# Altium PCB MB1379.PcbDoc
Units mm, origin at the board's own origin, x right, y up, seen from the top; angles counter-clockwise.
Board outline 29.13 x 44.63 mm, 2 copper layers (Top Layer, Bottom Layer), stack 1.571 mm thick; 39 components, 34 nets, 147 pads, 91 vias.
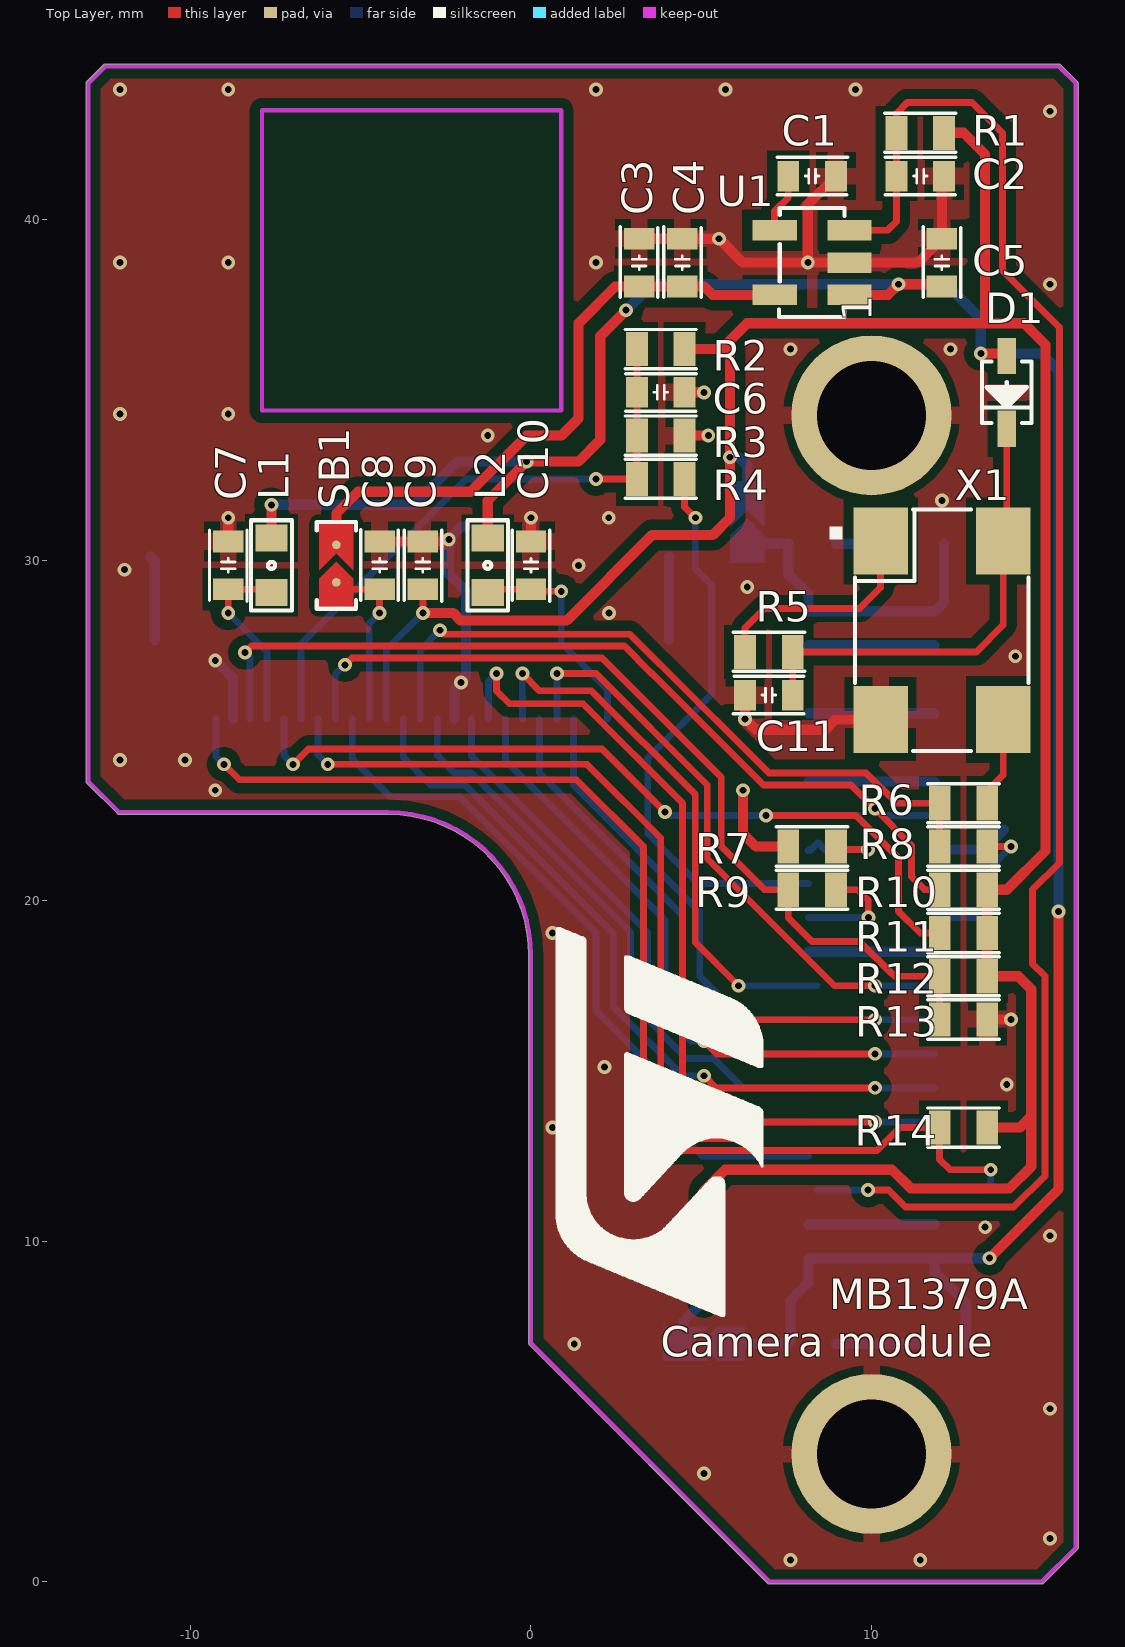
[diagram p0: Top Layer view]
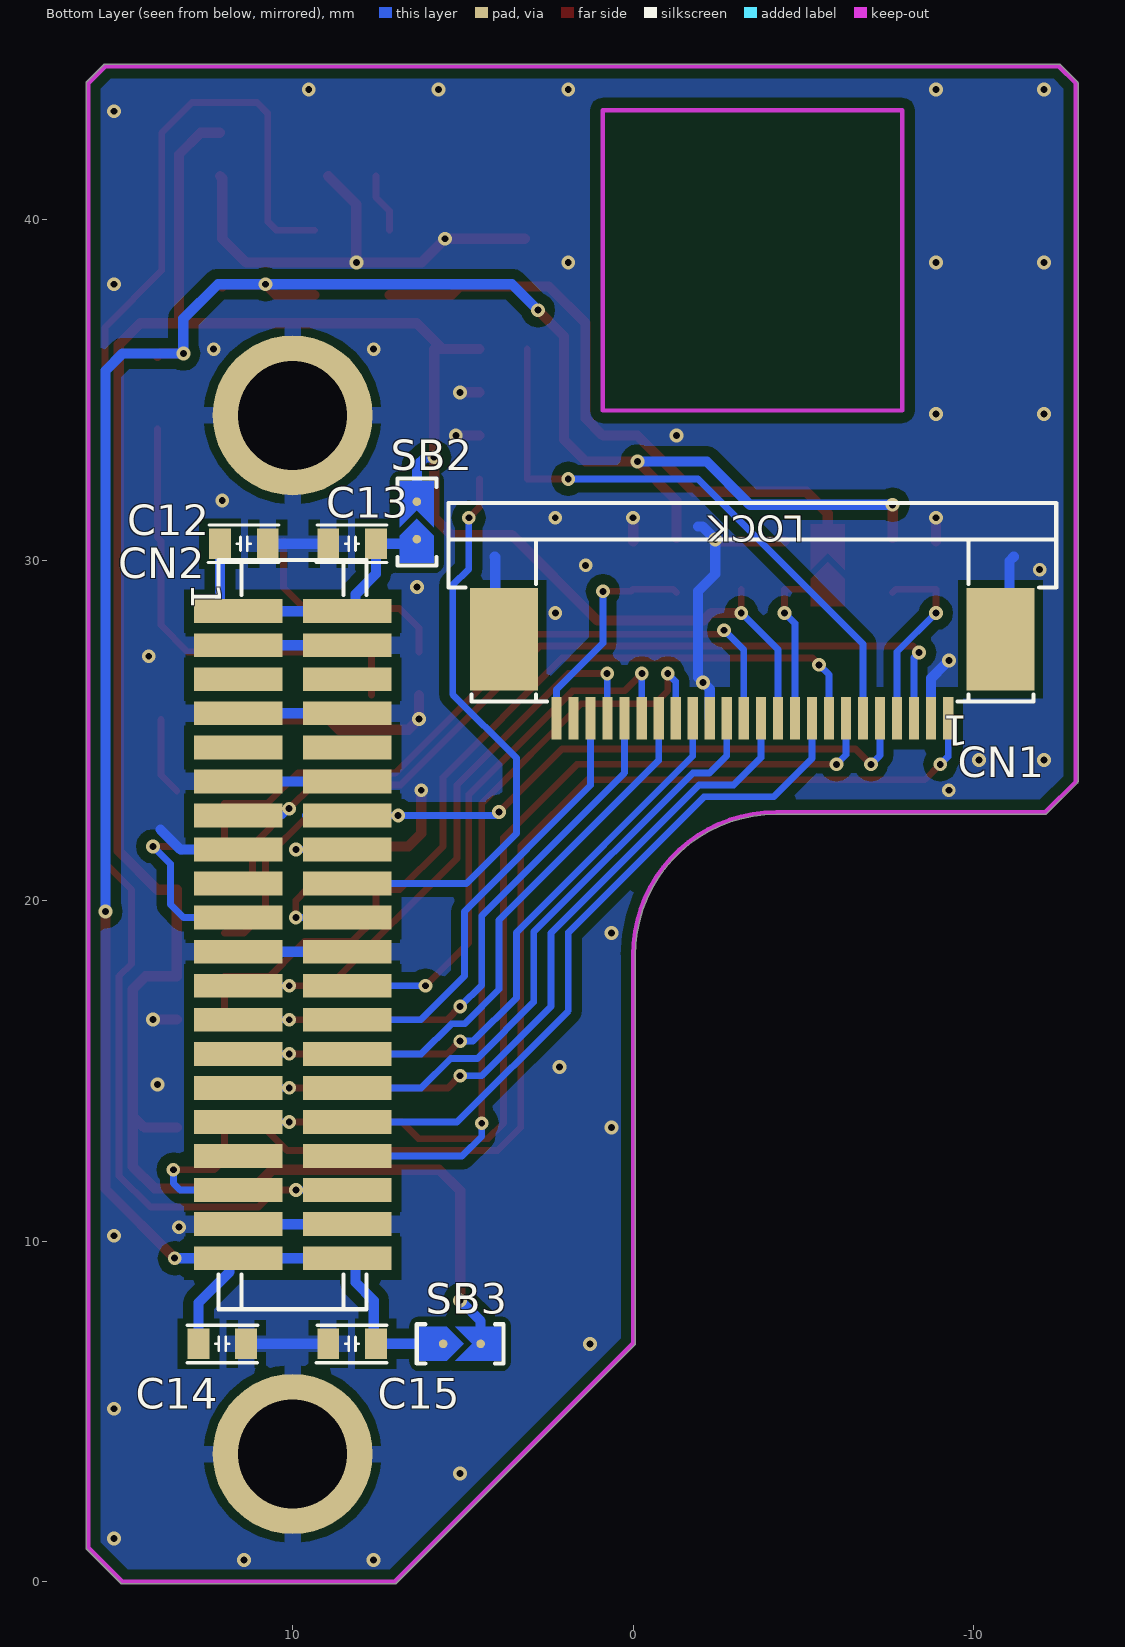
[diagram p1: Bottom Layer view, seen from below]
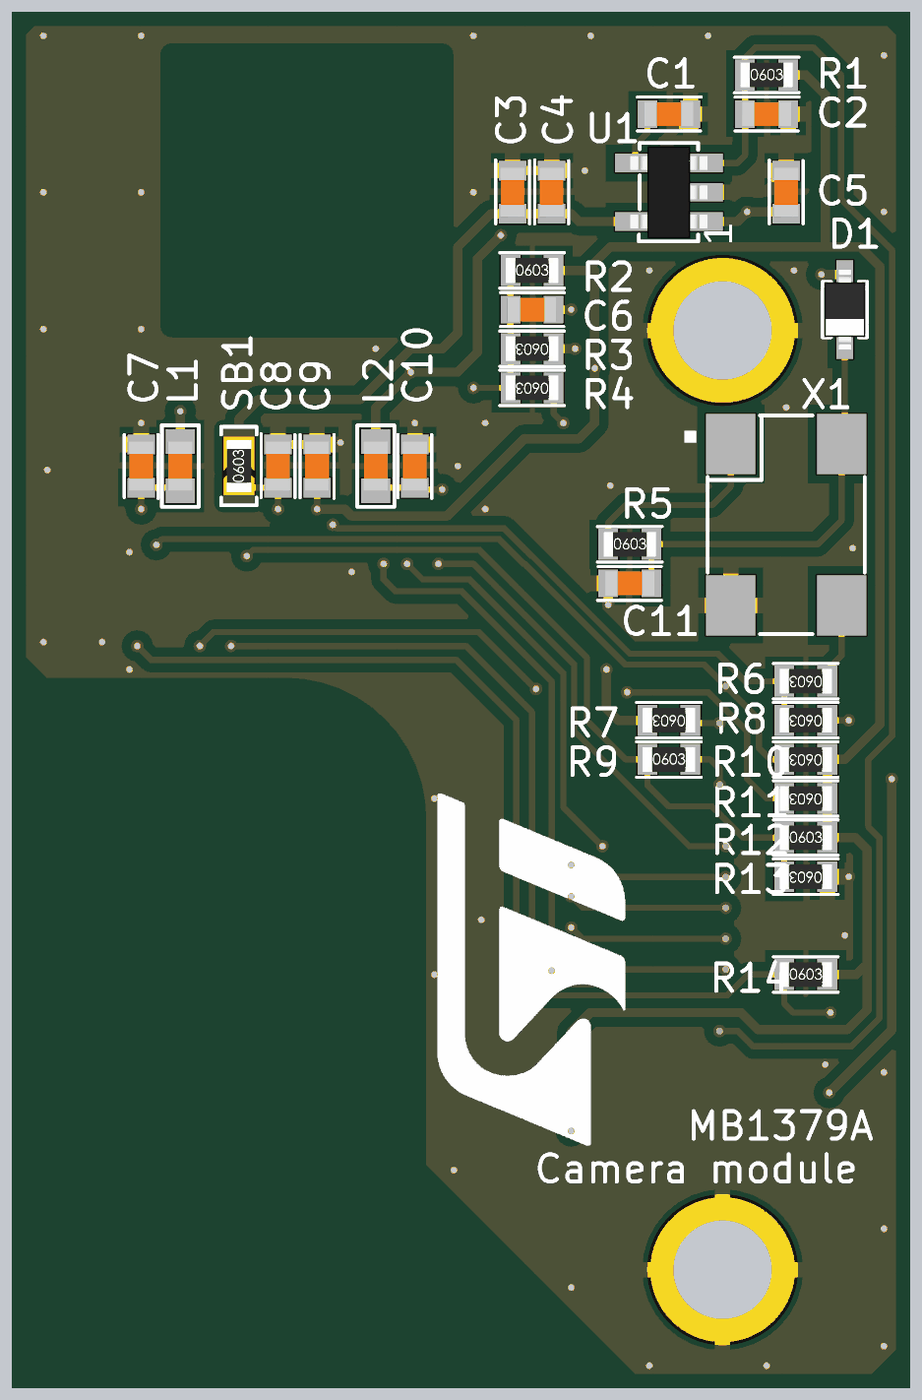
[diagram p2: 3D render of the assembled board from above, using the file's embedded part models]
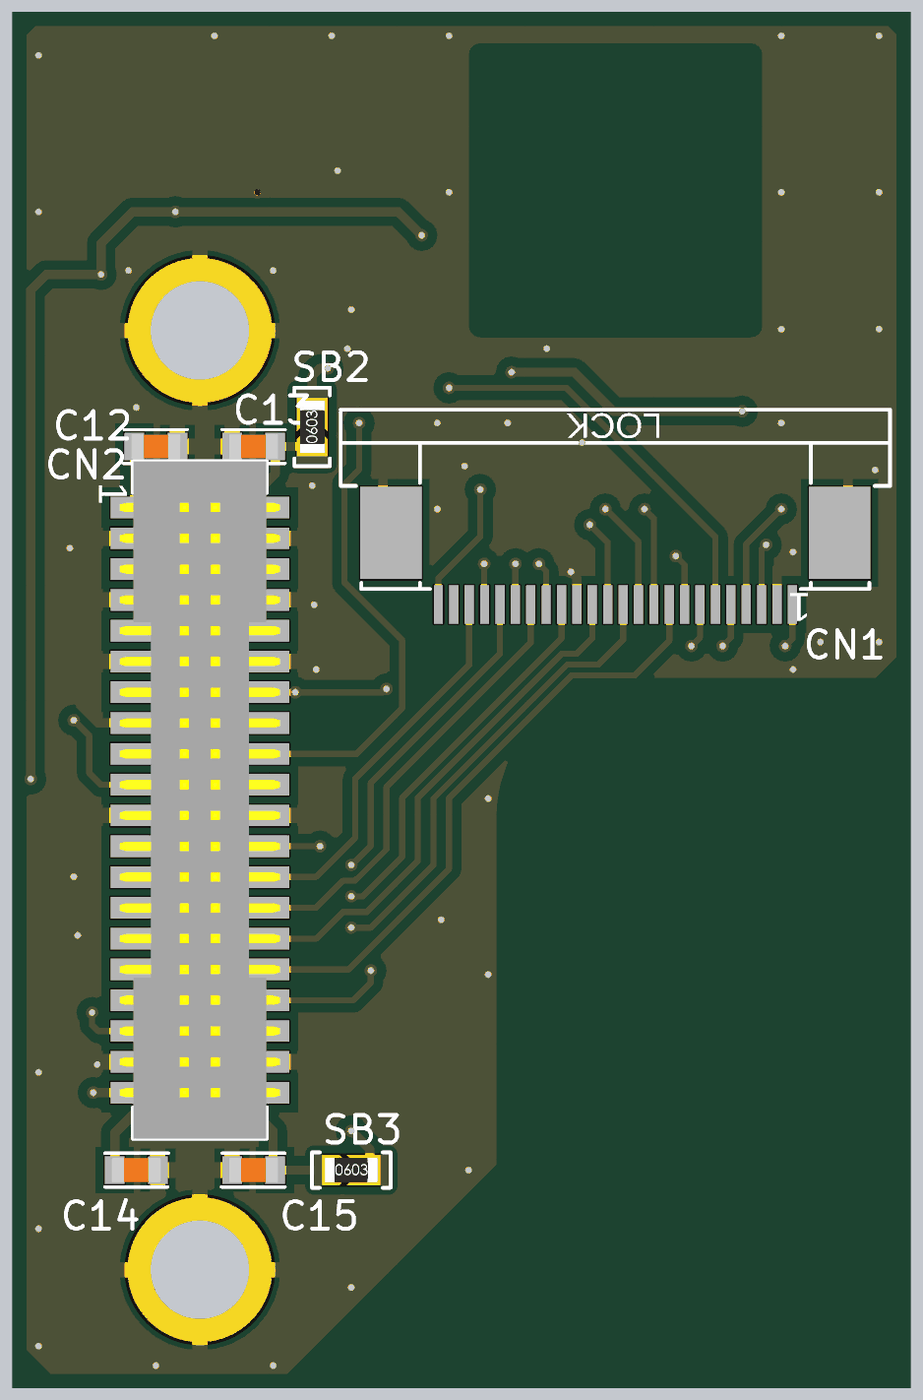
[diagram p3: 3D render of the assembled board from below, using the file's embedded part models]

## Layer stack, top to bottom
Top Solder: solder mask 0.0102, Solder Resist, Dk 3.5
Top Layer: signal copper 0.0356
Dielectric1: core 1.5, FR-4, Dk 4.8
Bottom Layer: signal copper 0.0356
Bottom Solder: solder mask 0.0102, Solder Resist, Dk 3.5

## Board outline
-12.1,22.536 -4.2,22.536 ccw(c-4.2,22.6) -4.199,22.536 cw(c-4.2,18.4) -0.064,18.4 ccw(c0,18.4) -0.064,18.399 -0.064,7 cw(c0,7) -0.064,7 ccw(c0,7) -0.045,6.955 cw(c0,7) -0.064,7 -0.045,6.955 6.955,-0.045 ccw(c7,0) 7,-0.064 15,-0.064 ccw(c15,0) 15.045,-0.045 16.045,0.955 ccw(c16,1) 16.064,1 16.064,44 ccw(c16,44) 16.045,44.045 15.545,44.545 ccw(c15.5,44.5) 15.5,44.564 -12.5,44.564 ccw(c-12.5,44.5) -12.545,44.545 -13.045,44.045 ccw(c-13,44) -13.064,44 -13.064,23.5 ccw(c-13,23.5) -13.045,23.455 -12.145,22.555 ccw(c-12.1,22.6)

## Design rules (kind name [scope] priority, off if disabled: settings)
Clearance Clearance_1 [(InPoly)] p1: gap=0.3
Clearance [All] p2: gap=0.15
FabricationTestPointUsage TestPointUsage [All] p1: valid=0 allowmultiple=FALSE
FabricationTestpoint Testpoint [(IsPad And (OnTopLayer Or OnBottomLayer))] p1: side=3 testpointundercomponent=TRUE minsize=1.016 maxsize=2.54 preferedsize=1.524 minholesize=0 maxholesize=1.016 preferedholesize=0.813 testpointgrid=0.025 allowsidetop=TRUE allowsidebottom=TRUE usegrid=TRUE gridtolerance=0
HoleSize [All] p1: absolutevalues=TRUE maxlimit=3.81 minlimit=0.025 maxpercent=80.000 minpercent=20.000
PlaneClearance [All] p1: clearance=0.5
PolygonConnect PolygonConnect_2 [(InComponent('CN1'))] p1: connectstyle=NoConnect reliefconductorwidth=0.254 reliefentries=2 polygonreliefangle="90 Angle" airgapwidth=0.254
PolygonConnect PolygonConnect_1 [IsVia] p2: connectstyle=Direct reliefconductorwidth=0.508 reliefentries=4 polygonreliefangle="90 Angle" airgapwidth=0.254
PolygonConnect [All] p3: connectstyle=Relief reliefconductorwidth=0.5 reliefentries=4 polygonreliefangle="90 Angle" airgapwidth=0.254
RoutingLayers [All] p1: top layer_v5=FALSE bottom layer_v5=FALSE
RoutingVias [All] p1: holewidth=0.3 width=0.6 viastyle="Through Hole" minholewidth=0.2 minwidth=0.4 maxholewidth=0.7 maxwidth=1.3
SolderMaskExpansion [All] p1: expansion=0.102
Width [All] p1: maxlimit=2.5 minlimit=0.15 preferedwidth=0.2 minimp=50.000000 maximp=50.000000 favimp=50.000000
25 further rules are at their usual default settings.

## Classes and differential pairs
net class PAR_D[0..7]: PAR_D0 PAR_D1 PAR_D2 PAR_D3 PAR_D4 PAR_D5 PAR_D6 PAR_D7

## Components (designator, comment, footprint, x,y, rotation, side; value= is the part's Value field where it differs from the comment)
C1 "" C0603 8.255,41.275 r180 top (schematic designator C66)
C2 "" C0603 11.43,41.275 r180 top (schematic designator C62)
C3 "" C0603 3.175,38.735 r270 top (schematic designator C68)
C4 "" C0603 4.445,38.735 r270 top (schematic designator C67)
C5 "" C0603 12.065,38.735 r270 top (schematic designator C61)
C6 "" C0603 3.81,34.925 r180 top (schematic designator C9)
C7 "" C0603 -8.89,29.845 r90 top (schematic designator C5)
C8 "" C0603 -4.445,29.845 r270 top (schematic designator C10)
C9 "" C0603 -3.175,29.845 r90 top (schematic designator C4)
C10 "" C0603 0,29.845 r90 top (schematic designator C3)
C11 "" C0603 6.985,26.035 r0 top (schematic designator C8)
C12 "" C0603 11.43,30.48 r180 bottom (schematic designator C2)
C13 "" C0603 8.255,30.48 r180 bottom (schematic designator C1)
C14 "" C0603 12.065,6.985 r0 bottom (schematic designator C7)
C15 "" C0603 8.255,6.985 r180 bottom (schematic designator C6)
CN1 "" CON_ATOM_FPC05024-03200 -3.5,30.6 r0 bottom (schematic designator CN2)
CN2 "" CON_SAMTEC_FTMH-120-03-L-DV-ES 10,19 r270 bottom (schematic designator CN1)
D1 "" DIO_SOD323 13.97,34.925 r270 top
L1 "" L0603 -7.62,29.845 r90 top
L2 "" L0603 -1.27,29.845 r90 top
R1 "" R0603 11.43,42.545 r0 top (schematic designator R10)
R2 "" R0603 3.81,36.195 r0 top
R3 "" R0603 3.81,33.655 r180 top (schematic designator R14)
R4 "" R0603 3.81,32.385 r180 top (schematic designator R13)
R5 "" R0603 6.985,27.305 r0 top (schematic designator R7)
R6 "" R0603 12.7,22.86 r180 top
R7 "" R0603 8.255,21.59 r180 top (schematic designator R3)
R8 "" R0603 12.7,21.59 r180 top (schematic designator R5)
R9 "" R0603 8.255,20.32 r0 top (schematic designator R12)
R10 "" R0603 12.7,20.32 r180 top (schematic designator R8)
R11 "" R0603 12.7,19.05 r180 top (schematic designator R9)
R12 "" R0603 12.7,17.78 r0 top (schematic designator R1)
R13 "" R0603 12.7,16.51 r180 top (schematic designator R4)
R14 "" R0603 12.7,13.335 r0 top (schematic designator R11)
SB1 "" SOLDER-BRIDGE_R0603-0R -5.715,29.845 r90 top
SB2 "" SOLDER-BRIDGE_R0603-0R 6.35,31.115 r90 bottom (schematic designator SB3)
SB3 "" SOLDER-BRIDGE_R0603-0R 5.08,6.985 r180 bottom (schematic designator SB2)
U1 "" REG_SOT23-5L 8.255,38.735 r90 top (schematic designator U2)
X1 "" OSC_PLE_SM77H-SERIES_7X5_H1P73_4P 12.065,27.94 r270 top

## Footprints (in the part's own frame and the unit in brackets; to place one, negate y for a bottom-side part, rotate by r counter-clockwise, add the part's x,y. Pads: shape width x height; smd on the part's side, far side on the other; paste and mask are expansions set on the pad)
C0603 [mm]
  rect 0.64x0.89 smd mask+0.05: 1(-0.7,0) 2(0.7,0)
  silkscreen extent -1.05,-0.55 1.02,0.55, body extent -0.9,-0.5 0.9,0.5, height 1.4
CON_ATOM_FPC05024-03200 [mm] "MCD-01009"
  rect 0.3x1.25 smd mask+0.05: 1(-5.75,5.25) 2(-5.25,5.25) 3(-4.75,5.25) 4(-4.25,5.25) 5(-3.75,5.25) 6(-3.25,5.25) 7(-2.75,5.25) 8(-2.25,5.25) 9(-1.75,5.25) 10(-1.25,5.25) 11(-0.75,5.25) 12(-0.25,5.25) 13(0.25,5.25) 14(0.75,5.25) 15(1.25,5.25) 16(1.75,5.25) 17(2.25,5.25) 18(2.75,5.25) 19(3.25,5.25) 20(3.75,5.25) 21(4.25,5.25) 22(4.75,5.25) 23(5.25,5.25) 24(5.75,5.25)
  rect 2x3 smd mask+0.05: 25(-7.29,2.925) 26(7.29,2.925)
  silkscreen extent -8.93,-1.07 8.93,4.75, body extent -8.93,-1.07 8.93,5.75, height 2.2
CON_SAMTEC_FTMH-120-03-L-DV-ES [mm] "MCD-01010"
  rect 0.7x2.6 smd mask+0.05: 1(-9.5,-1.6) 2(-9.5,1.6) 3(-8.5,-1.6) 4(-8.5,1.6) 5(-7.5,-1.6) 6(-7.5,1.6) 7(-6.5,-1.6) 8(-6.5,1.6) 9(-5.5,-1.6) 10(-5.5,1.6) 11(-4.5,-1.6) 12(-4.5,1.6) 13(-3.5,-1.6) 14(-3.5,1.6) 15(-2.5,-1.6) 16(-2.5,1.6) 17(-1.5,-1.6) 18(-1.5,1.6) 19(-0.5,-1.6) 20(-0.5,1.6) 21(0.5,-1.6) 22(0.5,1.6) 23(1.5,-1.6) 24(1.5,1.6) 25(2.5,-1.6) 26(2.5,1.6) 27(3.5,-1.6) 28(3.5,1.6) 29(4.5,-1.6) 30(4.5,1.6) 31(5.5,-1.6) 32(5.5,1.6) 33(6.5,-1.6) 34(6.5,1.6) 35(7.5,-1.6) 36(7.5,1.6) 37(8.5,-1.6) 38(8.5,1.6) 39(9.5,-1.6) 40(9.5,1.6)
  silkscreen extent -11,-2.17 11,2.17, body extent -11,-2.6 11,2.6, height 3.84
DIO_SOD323 [mm]
  rect 1.06x0.54 smd mask+0.05: 1(-1.07,0) 2(1.07,0)
  silkscreen extent -0.9,-0.72 0.9,0.72, body extent -1.3,-0.78 1.3,0.78, height 1.17
L0603 [mm]
  rect 0.8x0.95 smd mask+0.05: 1(-0.8,0) 2(0.8,0)
  silkscreen extent -1.33,-0.6 1.33,0.6, body extent -0.87,-0.47 0.87,0.47, height 0.95
OSC_PLE_SM77H-SERIES_7X5_H1P73_4P [mm]
  rect 1.96x1.6 smd mask+0.05: 1(-2.62,-1.8) 2(2.62,-1.8) 3(2.62,1.8) 4(-2.62,1.8)
  silkscreen extent -3.55,-3.3 3.55,2.55, body extent -3.55,-2.55 3.55,2.55, height 2.17
R0603 [mm]
  rect 0.64x1 smd mask+0.05: 1(-0.7,0) 2(0.7,0)
  silkscreen extent -1.05,-0.58 1.05,0.58, body extent -0.9,-0.5 0.9,0.5, height 0.56
REG_SOT23-5L [mm]
  rect 0.6x1.3 smd mask+0.05: 1(-0.95,-1.1) 2(0,-1.1) 3(0.95,-1.1) 4(0.95,1.1) 5(-0.95,1.1)
  silkscreen extent -1.6,-0.95 1.6,0.97, body extent -1.52,-1.25 1.52,1.25, height 1.1
SOLDER-BRIDGE_R0603-0R [mil]
  round 10 smd: 1(-19.68,0) 2(23.62,0)
  Top Layer region: -47.24,-19.69 -47.24,19.68 -15.75,19.68 3.94,0 -15.75,-19.69 -47.24,-19.69
  Top Layer region: -5.91,19.68 13.78,0 -5.91,-19.69 47.24,-19.69 47.24,19.68 -5.91,19.68
  silkscreen extent -50,-23 50,23, body extent -36,-20 36,20, height 22

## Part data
C1: library part MCD-01007, "Capacitor, MLCC, 10nF, 16V, X7R, 10%, 0603, T=0.8mm"
C2 C4 C7 C8 C9 C10 C11 C12 C13 C14 C15: library part MCD-00211, "Capacitor,100nF,16V,X7R,10%,0603"
C3 C5: library part MCD-00010, "Capacitor,1uF,16V,X5R,10%,0603"
C6: library part MCD-01006, "Capacitor, MLCC, 470nF, 16V, X7R, 10%, 0603, T=0.8mm"
CN1: library part MCD-01009, "FFC/FPC ZIF Connector -?0.5mm, 24 pins, Upper Contacts"
CN2: library part MCD-01010, "Header 20x2, 1mm, Dual Vertical,SMT,End Shroud,Height 3.25mm"
D1: library part MCD-00034, "BAT60JFILM"
L1 L2: library part MCD-00047, "SMD Chip ferrite bead, 600R@100MHz +/-25%, 350mA, 500mohm DC, 0603, T=0.8mm"
R1 R2 R3 R5 R13 R14: library part MCD-00220, "Resistor,10K,0603,1%,1/10W"
R4: library part MCD-00420, "Resistor,2K,0603,1%,1/10W"
R6 R7 R8 R9: library part MCD-00056, "Resistor,0R,0603,5%,1/10W"
R10 R11: library part MCD-00219, "Resistor,4K7,0603,1%,1/10W"
R12: library part MCD-00430, "Resistor,22K,0603,1%,1/10W"
SB1 SB3: library part MCD-00071, "Solder Bridge ON"
SB2: library part MCD-00072, "Solder Bridge OFF"
U1: library part MCD-01008, "LDO - 300 mA low quiescent current - very low noise"
X1: library part MCD-01011, "SM77H Series 2.5V? CMOS 24MHz Clock Oscillator"

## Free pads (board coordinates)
  round 4.7 hole 3.2: 0(10,3.75) 0(10,34.25)

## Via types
v1: diameter 0.406, hole 0.203, Top Layer to Bottom Layer, tented both sides, 75 vias
v2: diameter 0.4, hole 0.2, Top Layer to Bottom Layer, tented both sides, 16 vias

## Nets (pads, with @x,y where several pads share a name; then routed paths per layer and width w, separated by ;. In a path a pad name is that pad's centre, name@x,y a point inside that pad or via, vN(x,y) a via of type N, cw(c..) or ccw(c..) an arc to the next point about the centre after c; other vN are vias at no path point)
+1V8: C12.1 C13.2 CN2.1 CN2.2 SB2.1 | length 9.3
  Bottom Layer w0.3: SB2.1 6.485,30.48 C13.2 7.555,29.591 8.15,28.996 8.15,28.5 11.85,28.5 12.13,28.78 C12.1
+2V8: C5.2 C14.2 C15.2 CN2.39 CN2.40 D1.1 L1.2 L2.2 SB3.1 U1.1 | length 75.7
  Top Layer w0.3: L1.2 v1(-7.62,31.623) ; L2.2 -1.27,31.75 v1(-0.127,32.893) 1.397,32.893 2.032,33.528 2.032,36.576 v1(2.794,37.338) ; U1.1 10.48,37.785 v1(10.795,38.1) 12,38.1 C5.2 ; v1(13.208,36.068) 13.897,36.068 D1.1 ; v1(13.462,9.5) 15.494,11.532 v1(15.494,19.685)
  Bottom Layer w0.3: v1(-7.62,31.623) -3.429,31.623 -2.159,32.893 v1(-0.127,32.893) ; v1(2.794,37.338) 3.556,38.1 v1(10.795,38.1) 12.192,38.1 13.208,37.084 v1(13.208,36.068) 14.986,36.068 15.494,35.56 v1(15.494,19.685) ; 6.28,6.985 C15.2 7.62,7.05 7.62,8.255 8.15,8.785 8.15,9.5 CN2.39@11.85,9.5 ; C14.2 12.765,8.19 11.85,9.105 CN2.39@11.85,9.5 ; v1(13.462,9.5) CN2.39@11.85,9.5
CAMERA_CLK: CN1.13 R6.2 R8.2 | length 20.9
  Top Layer w0.2: v1(-2.667,27.94) -2.55,27.823 2.898,27.823 3.797,26.924 3.81,26.924 6.985,23.749 9.841,23.749 10.73,22.86 R6.2 R8.2
  Bottom Layer w0.2: CN1.13@-3.25,25.338 -3.25,27.357 v1(-2.667,27.94)
CAMERA_RST: CN2.18 R4.1 | length 16.8
  Top Layer w0.2: R4.1 4.51,31.558 v1(4.826,31.242)
  Bottom Layer w0.2: v1(4.826,31.242) 4.826,29.74 5.3,29.266 5.3,26.059 3.429,24.188 3.429,21.971 4.9,20.5 CN2.18@8.15,20.5
CAMERA_RST_S5K: C6.2 CN1.6 R2.1 R3.2 R4.2 | length 17.9
  Top Layer w0.2: v1(1.905,32.385) R4.2 R3.2 C6.2 R2.1
  Bottom Layer w0.2: CN1.6@-6.75,25.338 -6.75,27.54 -1.905,32.385 v1(1.905,32.385)
DOVDD: C9.1 CN1.11 R1.2 R2.2 R10.1 R11.1 R12.2 R14.2 SB2.2 SB3.2 | length 81.7
  Top Layer w0.2: v1(-3.175,28.448) C9.1
  Top Layer w0.3: v1(-3.175,28.448) -2.286,28.448 -2.061,28.223 1.045,28.223 3.561,30.739 3.566,30.734 5.334,30.734 5.842,31.242 v1(5.842,33.02) 5.842,36.195 R2.2 ; v1(5.08,8.255) 5.08,11.48 5.7,12.1 10.6,12.1 11.15,11.55 14.05,11.55 14.691,12.191 14.691,17.399 14.31,17.78 R12.2 R11.1 R10.1 13.97,20.32 15.108,21.458 15.108,36.327 14.478,36.957 13.335,36.957 ; 5.588,36.195 6.35,36.957 13.335,36.957 ; R1.2 12.7,42.545 13.335,41.91 13.335,36.957 ; R14.2 14.351,13.335 14.6,13.584
  Bottom Layer w0.2: CN1.11@-4.25,25.338 -4.25,27.373 v1(-3.175,28.448)
  Bottom Layer w0.3: SB3.2 4.48,7.655 v1(5.08,8.255) ; v1(5.842,33.02) 6.096,33.02 6.35,32.766 SB2.2
E1V5: C3.2 C4.2 SB1.2 U1.5 | length 18.3
  Top Layer w0.3: SB1.2 -5.715,31.369 -5.08,32.004 -1.778,32.004 -0.127,33.655 0.889,33.655 1.397,34.163 1.397,36.957 2.475,38.035 C3.2 C4.2 5.084,38.035 5.334,37.785 U1.5
EXTCLK: CN2.19 R8.1 | length 4.5
  Top Layer w0.203: R8.1 v1(14.097,21.59)
  Bottom Layer w0.203: CN2.19@11.85,19.5 13.208,19.5 13.589,19.881 13.589,21.082 v1(14.097,21.59)
FLASH: CN1.1 CN2.35 R14.1 | length 37.2
  Top Layer w0.2: v1(-9.017,24.003) -8.564,23.55 1.342,23.55 3.302,21.59 3.302,13.335 3.978,12.659 10.159,12.659 10.835,13.335 R14.1 12,12.4 12.3,12.1 v2(13.5,12.1)
  Bottom Layer w0.2: CN1.1@-9.25,25.338 -9.25,24.236 v1(-9.017,24.003) ; CN2.35 13.3,11.5 13.5,11.7 v2(13.5,12.1)
GND: C1.1 C2.1 C3.1 C4.1 C5.1 C6.1 C7.2 C8.1 C9.2 C10.2 C11.1 C12.2 C13.1 C14.1 C15.1 CN1.2 CN1.15 CN1.25 CN1.26 CN2.3 CN2.4 CN2.7 CN2.8 CN2.11 CN2.12 CN2.15 CN2.21 CN2.22 CN2.37 CN2.38 pad.0 R3.1 R7.2 R13.1 U1.2 X1.2 | length 65.2
  Top Layer w0.3: C7.2 v1(-8.89,31.242) ; C8.1 C9.2 -2.475,30.545 v1(-2.413,30.607) ; C10.2 v1(0,31.242) ; C3.1 C4.1 v1(5.523,39.435) 6.223,38.735 v1(8.128,38.735) ; R3.1 v1(5.207,33.655) ; C6.1 v1(5.08,34.925) ; v1(6.223,23.241) 6.223,21.971 6.604,21.59 R7.2 ; C11.1 v1(6.285,25.338) 6.604,25.019 8.636,25.019 8.937,25.32 X1.2 ; C1.1 8.128,40.448 v1(8.128,38.735) ; C2.1 12.065,41.21 C5.1 11.365,38.735 U1.2 v1(8.128,38.735) ; R13.1 v1(14.097,16.51)
  Bottom Layer w0.3: -11.176,30.099 -11.05,29.973 CN1.25@-11.05,27.662 ; v1@-9.144,26.924 -8.75,26.53 CN1.2@-8.75,25.338 ; CN1.15 -2.25,26.212 v1(-2.052,26.41) -1.905,26.557 -1.905,29.083 -2.413,29.591 v1(-2.413,30.607) -2.032,30.988 -1.905,30.988 ; CN1.26@4.05,27.662 4.05,30.085 4.064,30.099 ; CN2.38@8.15,10.5 CN2.37@11.85,10.5 ; CN2.22@8.15,18.5 CN2.22 CN2.21 CN2.21@11.85,18.5 ; CN2.12@8.15,23.5 CN2.11@11.85,23.5 ; CN2.8@8.15,25.5 CN2.7@11.85,25.5 ; CN2.4@8.15,27.5 CN2.3@11.85,27.5 ; C15.1 C14.1 ; C13.1 C12.2 ; CN2.15@11.85,21.5 13.295,21.5 13.88,22.085
  other v1: 7.62,0.635 11.43,0.635 15.24,1.27 5.08,3.175 15.24,5.08 1.27,6.985 15.24,10.16 0.635,13.335 13.97,14.605 2.159,15.113 0.635,19.05 -12.065,24.13 -10.16,24.13 -9.271,27.051 2.286,28.448 6.35,29.21 -11.938,29.718 12.065,31.75 -1.27,33.655 -12.065,34.29 -8.89,34.29 15.24,38.1 -12.065,38.735 -8.89,38.735 1.905,38.735 15.24,43.18 -12.065,43.815 -8.89,43.815 1.905,43.815 5.715,43.815 9.525,43.815
  other v2: 13.335,10.414 -9.271,23.241 14.224,27.178 1.397,29.845 2.286,31.242 7.62,36.195 12.319,36.195
NetC1_2: C1.2 U1.4 | length 1.8
  Top Layer w0.2: U1.4 7.155,40.248 7.555,40.648 C1.2
NetC7_1: C7.1 CN1.4 L1.1 | length 5.6
  Top Layer w0.2: v1(-8.89,28.448) C7.1 -7.72,29.145 L1.1
  Bottom Layer w0.2: v1(-8.89,28.448) -7.75,27.308 CN1.4@-7.75,25.338
NetC8_2: C8.2 CN1.10 SB1.1 | length 5.3
  Top Layer w0.2: SB1.1 -5.515,29.145 C8.2 v1(-4.445,28.448)
  Bottom Layer w0.2: CN1.10@-4.75,25.338 -4.75,28.143 v1(-4.445,28.448)
NetC10_1: C10.1 CN1.24 L2.1 | length 6.5
  Top Layer w0.2: L2.1 -1.17,29.145 C10.1 0.062,29.083 v1(0.889,29.083)
  Bottom Layer w0.2: v1(0.889,29.083) 0.889,27.559 2.25,26.198 CN1.24@2.25,25.338
NetC11_2: C11.2 D1.2 R5.2 X1.4 | length 13.6
  Top Layer w0.2: C11.2 R5.2 13.081,27.305 13.865,28.089 X1.4 13.97,30.665 D1.2
NetCN2_16: CN2.16 R7.1 | length 3
  Top Layer w0.2: R7.1 9.045,21.5 v1(9.9,21.5)
  Bottom Layer w0.2: CN2.16@8.128,21.463 8.15,21.485 8.15,21.5 8.187,21.463 8.424,21.7 8.624,21.5 v1(9.9,21.5)
NetCN2_20: CN2.20 R9.2 | length 3.3
  Top Layer w0.2: R9.2 9.586,20.32 9.906,20 v1(9.906,19.5)
  Bottom Layer w0.2: CN2.20@8.15,19.5 v1(9.906,19.5)
NetR5_1: R5.1 X1.1 | length 6.5
  Top Layer w0.2: R5.1 6.285,28.002 6.858,28.575 9.652,28.575 10.265,29.188 X1.1
NetR6_1: R6.1 X1.3 | length 2.3
  Top Layer w0.2: R6.1@13.4,23.223 13.865,23.687 X1.3
PAR_D0: CN1.19 CN2.24 | length 16.3
  Top Layer w0.2: v1(-0.254,26.67) 0.254,26.162 1.778,26.162 4.826,23.114 4.826,18.77 v1(6.096,17.5)
  Bottom Layer w0.2: v1(-0.254,26.67) CN1.19@-0.25,25.338 ; v1(6.096,17.5) CN2.24
PAR_D1: CN1.21 CN2.23 | length 19
  Top Layer w0.2: v1(0.762,26.67) 1.905,26.67 5.176,23.399 5.176,21.24 8.916,17.5 v2(10.1,17.5)
  Bottom Layer w0.2: CN1.21@0.75,25.338 0.762,25.349 v1(0.762,26.67) ; CN2.23 v2(10.1,17.5) CN2.23@11.85,17.5
PAR_D2: CN1.22 CN2.26 | length 12.8
  Bottom Layer w0.2: CN1.22@1.25,25.338 1.25,23.388 4.953,19.685 4.953,17.786 6.239,16.5 CN2.26@8.15,16.5
PAR_D3: CN1.20 CN2.25 | length 17.4
  Top Layer w0.2: v2(5.08,16.891) 5.471,16.5 v2(10.1,16.5)
  Bottom Layer w0.2: CN1.20@0.25,25.338 0.25,23.753 4.445,19.558 4.445,17.526 v2(5.08,16.891) ; v2(10.1,16.5) CN2.25 CN2.25@11.85,16.5
PAR_D4: CN1.18 CN2.28 | length 14.9
  Bottom Layer w0.2: CN1.18@-0.75,25.338 -0.75,24.118 3.937,19.431 3.937,17.398 4.894,16.441 4.898,16.441 4.956,16.383 5.34,16.383 6.223,15.5 CN2.28@8.15,15.5
PAR_D5: CN1.16 CN2.27 | length 19.4
  Top Layer w0.2: v2(5.08,15.875) 5.455,15.5 v2(10.1,15.5)
  Bottom Layer w0.2: CN1.16@-1.75,25.338 -1.75,24.242 3.429,19.063 3.429,17.145 4.699,15.875 v2(5.08,15.875) ; v2(10.1,15.5) CN2.27 CN2.27@11.85,15.5
PAR_D6: CN1.14 CN2.30 | length 17.2
  Bottom Layer w0.2: CN1.14@-2.75,25.338 -2.75,24.257 -2.242,23.749 -1.752,23.749 2.921,19.076 2.921,17.018 4.572,15.367 5.356,15.367 6.223,14.5 CN2.30@8.15,14.5
PAR_D7: CN1.12 CN2.29 | length 22
  Top Layer w0.2: v2(5.08,14.859) 5.439,14.5 v2(10.1,14.5)
  Bottom Layer w0.2: CN1.12@-3.75,25.338 -3.75,24.197 -2.952,23.399 -1.936,23.399 2.413,19.05 2.413,16.891 4.445,14.859 v2(5.08,14.859) ; v2(10.1,14.5) CN2.29 CN2.29@11.85,14.5
PAR_HSYNC: CN1.9 CN2.32 | length 20.3
  Bottom Layer w0.2: CN1.9 -5.25,24.173 -4.126,23.049 -2.081,23.049 1.905,19.063 1.905,16.764 5.169,13.5 CN2.32@8.15,13.5
PAR_PCLK: CN1.17 CN2.34 | length 22.5
  Top Layer w0.2: v1(-1.016,26.67) -1.016,26.162 -0.635,25.781 1.524,25.781 4.445,22.86 v1(4.445,13.462)
  Bottom Layer w0.2: CN1.17@-1.25,25.338 -1.25,26.436 v1(-1.016,26.67) ; v1(4.445,13.462) 4.445,13.081 5.026,12.5 CN2.34@8.15,12.5
PAR_VSYNC: CN1.7 CN2.31 | length 28.9
  Top Layer w0.2: v1(-5.969,24.003) 1.651,24.003 3.81,21.844 3.81,13.456 4.257,13.009 6.3,13.009 6.791,13.5 v2(10.1,13.5)
  Bottom Layer w0.2: CN1.7@-6.25,25.338 -6.25,24.284 v1(-5.969,24.003) ; v2(10.1,13.5) CN2.31 CN2.31@11.85,13.5
SCL: CN1.5 CN2.14 R11.2 | length 27.7
  Top Layer w0.2: v1(-6.985,24.003) -6.532,24.456 2.087,24.456 v1(3.937,22.606) ; v1(6.9,22.5) 9.541,22.5 10.795,21.246 10.795,19.685 11.43,19.05 R11.2
  Bottom Layer w0.2: CN1.5@-7.25,25.338 -7.25,24.268 v1(-6.985,24.003) ; v1(3.937,22.606) 4.043,22.5 v1(6.9,22.5) CN2.14 ; CN2.14 9.631,22.5 CN2.14
SDA: CN1.3 CN2.13 R10.2 | length 27.6
  Top Layer w0.2: v1(-8.397,27.29) -8.214,27.473 2.74,27.473 3.543,26.67 3.556,26.67 6.827,23.399 9.401,23.399 v1(10.1,22.7) 11.176,21.624 11.176,20.701 11.557,20.32 R10.2
  Bottom Layer w0.2: v1(-8.397,27.29) -8.25,27.142 CN1.3@-8.25,25.338 ; v1(10.1,22.7) 10.3,22.5 CN2.13
SHUTTER: C2.2 CN2.36 R1.1 U1.3 | length 47.3
  Top Layer w0.203: U1.3 10.475,39.685 10.73,39.94 C2.2 R1.1 10.73,43.115 11.049,43.434 12.954,43.434 13.843,42.545 13.843,38.502 15.515,36.83 15.515,21.103 14.732,20.32 14.732,18.14 15.092,17.78 15.092,11.917 14.175,11 11,11 10.5,11.5 v1(9.9,11.5)
  Bottom Layer w0.203: CN2.36 v1(9.9,11.5)
STANDBY: CN1.8 R9.1 R12.1 R13.2 | length 26.5
  Top Layer w0.2: v1(-5.461,26.924) -5.262,27.123 2.087,27.123 5.588,23.622 5.588,21.59 6.858,20.32 R9.1 7.555,19.496 8.255,18.796 9.652,18.796 10.668,17.78 R12.1 R13.2 R13.2@11.931,16.441 ; 10.286,18.15 10.55,17.886
  Bottom Layer w0.2: CN1.8@-5.75,25.338 -5.75,26.635 v1(-5.461,26.924)
pads on no net: CN1.23 CN2.5 CN2.6 CN2.9 CN2.10 CN2.17 CN2.33

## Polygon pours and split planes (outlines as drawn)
GND on Bottom Layer "Bottom Layer-No Net" (solid, remove dead copper, pour order 0): -13.081,44.45 15.875,44.45 16.002,44.577 16.002,0 -12.954,0 -13.081,-0.127 -13.081,44.45
GND on Top Layer "top Layer-GND" (solid, remove dead copper, pour order 2): -13.208,44.577 15.875,44.577 15.875,0.875 15,0 7,0 0,7 -13.208,20.208 -13.208,44.577

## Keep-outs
Keep-Out Layer:
  lines w0.127: -13,23.5 -12.1,22.6 -5.6,22.6 -4.2,22.6 cw(c-4.2,18.4) 0,18.4 0,7 7,0 15,0 16,1 16,39 16,44 15.5,44.5 -12.5,44.5 -13,44 -13,23.5 ; -7.899,34.392 -7.899,43.205 0.889,43.205 0.889,34.392 -7.899,34.392

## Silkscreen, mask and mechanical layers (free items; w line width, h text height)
Top Overlay:
  drawing of 1036 lines, arcs and shapes, not listed
  text "MB1379A" at 8.763,8.001 h0.89
  text "Camera module" at 3.81,6.604 h0.89
Mechanical 1:
  lines w0.127: 0,9 0,7 ; 0,7 7,0 15,0 16,1 16,39 16,44 15.5,44.5 -12.5,44.5 -13,44 -13,23.5 -12.1,22.6 -4.2,22.6 cw(c-4.2,18.4) 0,18.4 0,7 ; -7.9,34.4 0.9,34.4 0.9,43.2 -7.9,43.2 -7.9,34.4
  text "MB1379" at -12.192,44.831 h0.89
Drill Drawing:
  lines w0.051: 26.024,9.359 53.476,9.359 ; 26.024,10.347 53.476,10.347 ; 24.5,3.33 ccw(c24.83,3.33) 24.83,3 54.67,3 ccw(c54.67,3.33) 55,3.33 55,12.17 ccw(c54.67,12.17) 54.67,12.5 24.83,12.5 ccw(c24.83,12.17) 24.5,12.17 24.5,3.33
  text ".legend" at 19.5,39 h0.89
  text "Layer Stack Up Detail for: MB1379.PcbDoc" at 26.024,10.92 h0.66
  text "Layer" at 26.024,9.978 h0.23
  text "Gerber" at 32.02,9.978 h0.23
  text "Copper" at 34.791,9.978 h0.23
  text "Dielectric" at 37.936,9.978 h0.23
  text "Dielectric" at 41.24,9.978 h0.23
  text "Dielectric" at 45.585,9.978 h0.23
  text "Dielectric" at 48.89,9.978 h0.23
  text "Name" at 26.024,9.521 h0.23
  text "Document" at 32.02,9.521 h0.23
  text "Thickness" at 34.791,9.521 h0.23
  text "Height" at 37.936,9.521 h0.23
  text "Material" at 41.24,9.521 h0.23
  text "Constant" at 45.585,9.521 h0.23
  text "Type" at 48.89,9.521 h0.23
  text "Top Solder Mask" at 26.024,8.74 h0.33
  text "(.GTS)" at 32.02,8.74 h0.33
  text "0.4mil" at 37.936,8.74 h0.33
  text "Solder Resist" at 41.24,8.74 h0.33
  text "3.50" at 45.585,8.74 h0.33
  text "Top Layer" at 26.024,7.552 h0.33
  text "(.GTL)" at 32.02,7.552 h0.33
  text "1.4mil" at 34.791,7.552 h0.33
  text "59.055mil" at 37.936,6.958 h0.33
  text "FR-4" at 41.24,6.958 h0.33
  text "4.80" at 45.585,6.958 h0.33
  text "Core" at 48.89,6.958 h0.33
  text "Bottom Layer" at 26.024,6.365 h0.33
  text "(.GBL)" at 32.02,6.365 h0.33
  text "1.4mil" at 34.791,6.365 h0.33
  text "Bottom Solder Mask" at 26.024,5.177 h0.33
  text "(.GBS)" at 32.02,5.177 h0.33
  text "0.4mil" at 37.936,5.177 h0.33
  text "Solder Resist" at 41.24,5.177 h0.33
  text "3.50" at 45.585,5.177 h0.33

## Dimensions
7,0 to 16,1 on Mechanical 1
7,0 to 0,7 on Mechanical 1
-12.5,44.5 to -12.1,22.6 on Mechanical 1
-12.5,44.5 to 7,0 on Mechanical 1
-13,44 to 16,39 on Mechanical 1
